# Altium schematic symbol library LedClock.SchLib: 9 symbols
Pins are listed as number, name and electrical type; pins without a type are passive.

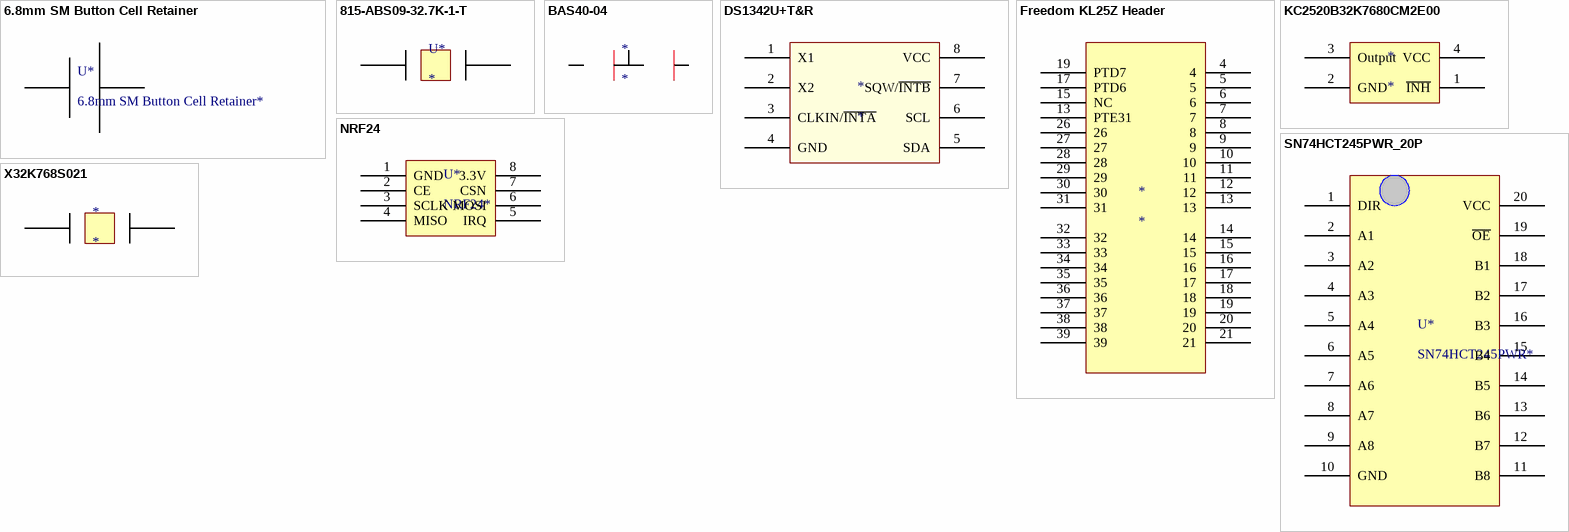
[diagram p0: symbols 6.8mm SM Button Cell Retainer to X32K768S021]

## 6.8mm SM Button Cell Retainer
designator U*, comment 6.8mm SM Button Cell Retainer*
footprint 6.8mm SM Button Cell Retainer
pins: 1, 2

## 815-ABS09-32.7K-1-T
designator U*
815-ABS09-32.7K-1-T
pins: 1, 2

## BAS40-04
designator *
footprint SOT23 (SOT-23)
pins: 1, 2, 3

## DS1342U+T&R
designator *
footprint uSOP-8 (3x3mm, 0.65mm)
pins: 1 X1, 2 X2, 3 CLKIN/~{INTA}, 4 GND, 5 SDA, 6 SCL, 7 SQW/~{INTB}, 8 VCC

## Freedom KL25Z Header
designator *
pins: 4, 5, 6, 7, 8, 9, 10, 11, 12, 13, 13 PTE31, 14, 15, 15 NC, 16, 17, 17 PTD6, 18, 19, 19 PTD7, 20, 21, 26, 27, 28, 29, 30, 31, 32, 33, 34, 35, 36, 37, 38, 39

## KC2520B32K7680CM2E00
designator *
footprint KC2520B32K7680CM2E00_4P
pins: 1 ~{INH}, 2 GND, 3 Output, 4 VCC

## NRF24
designator U*, comment NRF24*
footprint HEADER2X4 (Header 8Pin, 2x4, RM 2.54mm); pin to pad 2>8 3>2 4>7 5>3 7>4 8>5
pins: 1 GND, 2 CE, 3 SCLK, 4 MISO, 5 IRQ, 6 MOSI, 7 CSN, 8 3.3V

## SN74HCT245PWR_20P
designator U*, comment SN74HCT245PWR*
footprint SN74HCT245PWR_20P
pins: 1 DIR, 2 A1, 3 A2, 4 A3, 5 A4, 6 A5, 7 A6, 8 A7, 9 A8, 10 GND, 11 B8, 12 B7, 13 B6, 14 B5, 15 B4, 16 B3, 17 B2, 18 B1, 19 ~{OE}, 20 VCC

## X32K768S021
designator *
footprint X32K768S021
pins: 1, 2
